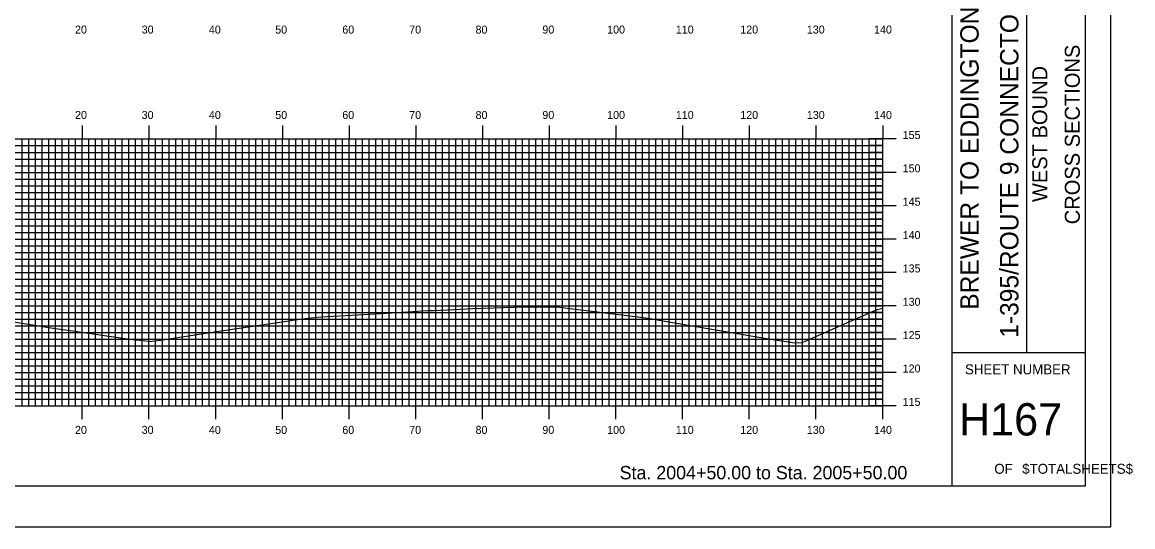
# Model space of a CAD drawing. Extents: x 851926 to 852269, y 366605 to 366825.
# Drawn here: x 852103 to 852269.5, y 366604.9 to 366680.6 of the extents above; entities that cross this region are included whole.
import ezdxf

# ---------------------------------------------------------------- set-up
doc = ezdxf.new("R2010")
doc.units = 0
for name, color, linetype in [('BORDER', 7, 'Continuous'), ('H_V ANNOTATION', 7, 'Continuous'), ('M_Roadway_Centerline', 7, 'Continuous'), ('MAJOR', 7, 'Continuous'), ('MINOR', 7, 'Continuous'), ('PLOT BOUNDARY', 7, 'Continuous'), ('S_Roadway_Centerline', 7, 'Continuous')]:
    doc.layers.add(name, color=color, linetype=linetype)

msp = doc.modelspace()

# ---------------------------------------------------------------- linework, layer by layer
at = {"layer": 'BORDER'}
for p, q in [((852242.36, 366611.06), (852242.36, 366821.06)), ((852253.55, 366631.06), (852253.55, 366701.06)), ((852242.36, 366631.06), (852262.36, 366631.06))]:
    msp.add_line(p, q, dxfattribs=at)
msp.add_lwpolyline([(851942.36, 366611.06), (852262.36, 366611.06), (852262.36, 366821.06), (851942.36, 366821.06)], close=True, dxfattribs=at)
at = {"layer": 'MAJOR'}
for p, q in [((852111.96, 366665.06), (852111.96, 366663.06)), ((852121.96, 366665.06), (852121.96, 366663.06)), ((852131.96, 366665.06), (852131.96, 366663.06)), ((852141.96, 366665.06), (852141.96, 366663.06)), ((852151.96, 366665.06), (852151.96, 366663.06)), ((852161.96, 366665.06), (852161.96, 366663.06)), ((852171.96, 366665.06), (852171.96, 366663.06)), ((852181.96, 366665.06), (852181.96, 366663.06)), ((852191.96, 366665.06), (852191.96, 366663.06)), ((852201.96, 366665.06), (852201.96, 366663.06)), ((852211.96, 366665.06), (852211.96, 366663.06)), ((852221.96, 366665.06), (852221.96, 366663.06)), ((852231.96, 366665.06), (852231.96, 366663.06)), ((851951.96, 366663.06), (852231.96, 366663.06)), ((851951.96, 366663.06), (852231.96, 366663.06)), ((852111.96, 366623.06), (852111.96, 366663.06)), ((852121.96, 366623.06), (852121.96, 366663.06)), ((852131.96, 366623.06), (852131.96, 366663.06)), ((852141.96, 366623.06), (852141.96, 366663.06)), ((852151.96, 366623.06), (852151.96, 366663.06)), ((852161.96, 366623.06), (852161.96, 366663.06)), ((852171.96, 366623.06), (852171.96, 366663.06)), ((852181.96, 366623.06), (852181.96, 366663.06)), ((852191.96, 366623.06), (852191.96, 366663.06)), ((852201.96, 366623.06), (852201.96, 366663.06)), ((852211.96, 366623.06), (852211.96, 366663.06)), ((852221.96, 366623.06), (852221.96, 366663.06)), ((852233.97, 366663.06), (852229.96, 366663.06)), ((852231.96, 366623.06), (852231.96, 366663.06)), ((852231.96, 366623.06), (852231.96, 366663.06)), ((851951.96, 366658.06), (852231.96, 366658.06)), ((852233.97, 366658.06), (852229.96, 366658.06)), ((851951.96, 366653.06), (852231.96, 366653.06)), ((852233.97, 366653.06), (852229.96, 366653.06)), ((851951.96, 366648.06), (852231.96, 366648.06)), ((852233.97, 366648.06), (852229.96, 366648.06)), ((851951.96, 366643.06), (852231.96, 366643.06)), ((852233.97, 366643.06), (852229.96, 366643.06)), ((851951.96, 366638.06), (852231.96, 366638.06)), ((852233.97, 366638.06), (852229.96, 366638.06)), ((851951.96, 366633.06), (852231.96, 366633.06)), ((852233.97, 366633.06), (852229.96, 366633.06)), ((851951.96, 366628.06), (852231.96, 366628.06)), ((852233.97, 366628.06), (852229.96, 366628.06)), ((851951.96, 366623.06), (852231.96, 366623.06)), ((851951.96, 366623.06), (852231.96, 366623.06)), ((852111.96, 366621.05), (852111.96, 366623.06)), ((852121.96, 366621.05), (852121.96, 366623.06)), ((852131.96, 366621.05), (852131.96, 366623.06)), ((852141.96, 366621.05), (852141.96, 366623.06)), ((852151.96, 366621.05), (852151.96, 366623.06)), ((852161.96, 366621.05), (852161.96, 366623.06)), ((852171.96, 366621.05), (852171.96, 366623.06)), ((852181.96, 366621.05), (852181.96, 366623.06)), ((852191.96, 366621.05), (852191.96, 366623.06)), ((852201.96, 366621.05), (852201.96, 366623.06)), ((852211.96, 366621.05), (852211.96, 366623.06)), ((852221.96, 366621.05), (852221.96, 366623.06)), ((852233.97, 366623.06), (852229.96, 366623.06)), ((852231.96, 366621.05), (852231.96, 366623.06))]:
    msp.add_line(p, q, dxfattribs=at)
at = {"layer": 'MINOR'}
for p, q in [((852102.96, 366623.06), (852102.96, 366663.06)), ((852103.96, 366623.06), (852103.96, 366663.06)), ((852104.96, 366623.06), (852104.96, 366663.06)), ((852105.96, 366623.06), (852105.96, 366663.06)), ((852106.96, 366623.06), (852106.96, 366663.06)), ((852107.96, 366623.06), (852107.96, 366663.06)), ((852108.96, 366623.06), (852108.96, 366663.06)), ((852109.96, 366623.06), (852109.96, 366663.06)), ((852110.96, 366623.06), (852110.96, 366663.06)), ((852112.96, 366623.06), (852112.96, 366663.06)), ((852113.96, 366623.06), (852113.96, 366663.06)), ((852114.96, 366623.06), (852114.96, 366663.06)), ((852115.96, 366623.06), (852115.96, 366663.06)), ((852116.96, 366623.06), (852116.96, 366663.06)), ((852117.96, 366623.06), (852117.96, 366663.06)), ((852118.96, 366623.06), (852118.96, 366663.06)), ((852119.96, 366623.06), (852119.96, 366663.06)), ((852120.96, 366623.06), (852120.96, 366663.06)), ((852122.96, 366623.06), (852122.96, 366663.06)), ((852123.96, 366623.06), (852123.96, 366663.06)), ((852124.96, 366623.06), (852124.96, 366663.06)), ((852125.96, 366623.06), (852125.96, 366663.06)), ((852126.96, 366623.06), (852126.96, 366663.06)), ((852127.96, 366623.06), (852127.96, 366663.06)), ((852128.96, 366623.06), (852128.96, 366663.06)), ((852129.96, 366623.06), (852129.96, 366663.06)), ((852130.96, 366623.06), (852130.96, 366663.06)), ((852132.96, 366623.06), (852132.96, 366663.06)), ((852133.96, 366623.06), (852133.96, 366663.06)), ((852134.96, 366623.06), (852134.96, 366663.06)), ((852135.96, 366623.06), (852135.96, 366663.06)), ((852136.96, 366623.06), (852136.96, 366663.06)), ((852137.96, 366623.06), (852137.96, 366663.06)), ((852138.96, 366623.06), (852138.96, 366663.06)), ((852139.96, 366623.06), (852139.96, 366663.06)), ((852140.96, 366623.06), (852140.96, 366663.06)), ((852142.96, 366623.06), (852142.96, 366663.06)), ((852143.96, 366623.06), (852143.96, 366663.06)), ((852144.96, 366623.06), (852144.96, 366663.06)), ((852145.96, 366623.06), (852145.96, 366663.06)), ((852146.96, 366623.06), (852146.96, 366663.06)), ((852147.96, 366623.06), (852147.96, 366663.06)), ((852148.96, 366623.06), (852148.96, 366663.06)), ((852149.96, 366623.06), (852149.96, 366663.06)), ((852150.96, 366623.06), (852150.96, 366663.06)), ((852152.96, 366623.06), (852152.96, 366663.06)), ((852153.96, 366623.06), (852153.96, 366663.06)), ((852154.96, 366623.06), (852154.96, 366663.06)), ((852155.96, 366623.06), (852155.96, 366663.06)), ((852156.96, 366623.06), (852156.96, 366663.06)), ((852157.96, 366623.06), (852157.96, 366663.06)), ((852158.96, 366623.06), (852158.96, 366663.06)), ((852159.96, 366623.06), (852159.96, 366663.06)), ((852160.96, 366623.06), (852160.96, 366663.06)), ((852162.96, 366623.06), (852162.96, 366663.06)), ((852163.96, 366623.06), (852163.96, 366663.06)), ((852164.96, 366623.06), (852164.96, 366663.06)), ((852165.96, 366623.06), (852165.96, 366663.06)), ((852166.96, 366623.06), (852166.96, 366663.06)), ((852167.96, 366623.06), (852167.96, 366663.06)), ((852168.96, 366623.06), (852168.96, 366663.06)), ((852169.96, 366623.06), (852169.96, 366663.06)), ((852170.96, 366623.06), (852170.96, 366663.06)), ((852172.96, 366623.06), (852172.96, 366663.06)), ((852173.96, 366623.06), (852173.96, 366663.06)), ((852174.96, 366623.06), (852174.96, 366663.06)), ((852175.96, 366623.06), (852175.96, 366663.06)), ((852176.96, 366623.06), (852176.96, 366663.06)), ((852177.96, 366623.06), (852177.96, 366663.06)), ((852178.96, 366623.06), (852178.96, 366663.06)), ((852179.96, 366623.06), (852179.96, 366663.06)), ((852180.96, 366623.06), (852180.96, 366663.06)), ((852182.96, 366623.06), (852182.96, 366663.06)), ((852183.96, 366623.06), (852183.96, 366663.06)), ((852184.96, 366623.06), (852184.96, 366663.06)), ((852185.96, 366623.06), (852185.96, 366663.06)), ((852186.96, 366623.06), (852186.96, 366663.06)), ((852187.96, 366623.06), (852187.96, 366663.06)), ((852188.96, 366623.06), (852188.96, 366663.06)), ((852189.96, 366623.06), (852189.96, 366663.06)), ((852190.96, 366623.06), (852190.96, 366663.06)), ((852192.96, 366623.06), (852192.96, 366663.06)), ((852193.96, 366623.06), (852193.96, 366663.06)), ((852194.96, 366623.06), (852194.96, 366663.06)), ((852195.96, 366623.06), (852195.96, 366663.06)), ((852196.96, 366623.06), (852196.96, 366663.06)), ((852197.96, 366623.06), (852197.96, 366663.06)), ((852198.96, 366623.06), (852198.96, 366663.06)), ((852199.96, 366623.06), (852199.96, 366663.06)), ((852200.96, 366623.06), (852200.96, 366663.06)), ((852202.96, 366623.06), (852202.96, 366663.06)), ((852203.96, 366623.06), (852203.96, 366663.06)), ((852204.96, 366623.06), (852204.96, 366663.06)), ((852205.96, 366623.06), (852205.96, 366663.06)), ((852206.96, 366623.06), (852206.96, 366663.06)), ((852207.96, 366623.06), (852207.96, 366663.06)), ((852208.96, 366623.06), (852208.96, 366663.06)), ((852209.96, 366623.06), (852209.96, 366663.06)), ((852210.96, 366623.06), (852210.96, 366663.06)), ((852212.96, 366623.06), (852212.96, 366663.06)), ((852213.96, 366623.06), (852213.96, 366663.06)), ((852214.96, 366623.06), (852214.96, 366663.06)), ((852215.96, 366623.06), (852215.96, 366663.06)), ((852216.96, 366623.06), (852216.96, 366663.06)), ((852217.96, 366623.06), (852217.96, 366663.06)), ((852218.96, 366623.06), (852218.96, 366663.06)), ((852219.96, 366623.06), (852219.96, 366663.06)), ((852220.96, 366623.06), (852220.96, 366663.06)), ((852222.96, 366623.06), (852222.96, 366663.06)), ((852223.96, 366623.06), (852223.96, 366663.06)), ((852224.96, 366623.06), (852224.96, 366663.06)), ((852225.96, 366623.06), (852225.96, 366663.06)), ((852226.96, 366623.06), (852226.96, 366663.06)), ((852227.96, 366623.06), (852227.96, 366663.06)), ((852228.96, 366623.06), (852228.96, 366663.06)), ((852229.96, 366623.06), (852229.96, 366663.06)), ((852230.96, 366623.06), (852230.96, 366663.06)), ((851951.96, 366662.06), (852231.96, 366662.06)), ((851951.96, 366661.06), (852231.96, 366661.06)), ((852231.96, 366662.06), (852229.96, 366662.06)), ((852231.96, 366661.06), (852229.96, 366661.06)), ((851951.96, 366660.06), (852231.96, 366660.06)), ((852231.96, 366660.06), (852229.96, 366660.06)), ((851951.96, 366659.06), (852231.96, 366659.06)), ((852231.96, 366659.06), (852229.96, 366659.06)), ((851951.96, 366657.06), (852231.96, 366657.06)), ((851951.96, 366656.06), (852231.96, 366656.06)), ((852231.96, 366657.06), (852229.96, 366657.06)), ((852231.96, 366656.06), (852229.96, 366656.06)), ((851951.96, 366655.06), (852231.96, 366655.06)), ((852231.96, 366655.06), (852229.96, 366655.06)), ((851951.96, 366654.06), (852231.96, 366654.06)), ((852231.96, 366654.06), (852229.96, 366654.06)), ((851951.96, 366652.06), (852231.96, 366652.06)), ((851951.96, 366651.06), (852231.96, 366651.06)), ((852231.96, 366652.06), (852229.96, 366652.06)), ((852231.96, 366651.06), (852229.96, 366651.06)), ((851951.96, 366650.06), (852231.96, 366650.06)), ((852231.96, 366650.06), (852229.96, 366650.06)), ((851951.96, 366649.06), (852231.96, 366649.06)), ((852231.96, 366649.06), (852229.96, 366649.06)), ((851951.96, 366647.06), (852231.96, 366647.06)), ((851951.96, 366646.06), (852231.96, 366646.06)), ((852231.96, 366647.06), (852229.96, 366647.06)), ((852231.96, 366646.06), (852229.96, 366646.06)), ((851951.96, 366645.06), (852231.96, 366645.06)), ((852231.96, 366645.06), (852229.96, 366645.06)), ((851951.96, 366644.06), (852231.96, 366644.06)), ((852231.96, 366644.06), (852229.96, 366644.06)), ((851951.96, 366642.06), (852231.96, 366642.06)), ((851951.96, 366641.06), (852231.96, 366641.06)), ((852231.96, 366642.06), (852229.96, 366642.06)), ((852231.96, 366641.06), (852229.96, 366641.06)), ((851951.96, 366640.06), (852231.96, 366640.06)), ((852231.96, 366640.06), (852229.96, 366640.06)), ((851951.96, 366639.06), (852231.96, 366639.06)), ((852231.96, 366639.06), (852229.96, 366639.06)), ((851951.96, 366637.06), (852231.96, 366637.06)), ((851951.96, 366636.06), (852231.96, 366636.06)), ((852231.96, 366637.06), (852229.96, 366637.06)), ((852231.96, 366636.06), (852229.96, 366636.06)), ((851951.96, 366635.06), (852231.96, 366635.06)), ((852231.96, 366635.06), (852229.96, 366635.06)), ((851951.96, 366634.06), (852231.96, 366634.06)), ((852231.96, 366634.06), (852229.96, 366634.06)), ((851951.96, 366632.06), (852231.96, 366632.06)), ((851951.96, 366631.06), (852231.96, 366631.06)), ((852231.96, 366632.06), (852229.96, 366632.06)), ((852231.96, 366631.06), (852229.96, 366631.06)), ((851951.96, 366630.06), (852231.96, 366630.06)), ((852231.96, 366630.06), (852229.96, 366630.06)), ((851951.96, 366629.06), (852231.96, 366629.06)), ((852231.96, 366629.06), (852229.96, 366629.06)), ((851951.96, 366627.06), (852231.96, 366627.06)), ((851951.96, 366626.06), (852231.96, 366626.06)), ((852231.96, 366627.06), (852229.96, 366627.06)), ((852231.96, 366626.06), (852229.96, 366626.06)), ((851951.96, 366625.06), (852231.96, 366625.06)), ((852231.96, 366625.06), (852229.96, 366625.06)), ((851951.96, 366624.06), (852231.96, 366624.06)), ((852231.96, 366624.06), (852229.96, 366624.06))]:
    msp.add_line(p, q, dxfattribs=at)
at = {"layer": 'PLOT BOUNDARY'}
msp.add_lwpolyline([(851926.18, 366604.94), (852266.18, 366604.94), (852266.18, 366824.94), (851926.18, 366824.94)], close=True, dxfattribs=at)
at = {"layer": 'S_Roadway_Centerline'}
msp.add_lwpolyline([(852096.8, 366636.39), (852104.84, 366635.14), (852106.94, 366634.82), (852110.51, 366634.31), (852119.09, 366633.07), (852121.92, 366632.77), (852121.98, 366632.71), (852123.66, 366632.93), (852132.07, 366634.21), (852141.25, 366635.56), (852144.89, 366636.08), (852147.72, 366636.42), (852153.26, 366636.71), (852154.99, 366636.8), (852159.27, 366637.03), (852163.74, 366637.36), (852164.72, 366637.37), (852170.5, 366637.65), (852178.19, 366637.9), (852182.52, 366637.91), (852183.27, 366637.89), (852183.85, 366637.82), (852196.03, 366636.3), (852196.86, 366636.19), (852198.98, 366635.81), (852214.86, 366633.11), (852218.77, 366632.53), (852219.88, 366632.57), (852230.32, 366637.15), (852231.2, 366637.51), (852231.96, 366637.71)], dxfattribs=at)

# ---------------------------------------------------------------- texts
at = {"layer": 'BORDER'}
for s, height, p in [('1-395/ROUTE 9 CONNECTOR', 2.7557, (852252.32, 366633.26)), ('BREWER TO EDDINGTON', 2.7557, (852246.35, 366637.46)), ('CROSS SECTIONS', 2.25, (852261.52, 366650.28)), ('WEST BOUND', 2.25, (852256.64, 366653.61))]:
    msp.add_text(s, height=height, rotation=90, dxfattribs=at).set_placement(p)
for s, height, p in [('SHEET NUMBER', 1.4905, (852244.3, 366627.79)), ('H167', 4.839, (852243.4, 366618.62)), ('OF', 1.491, (852248.7, 366612.88)), ('$TOTALSHEETS$', 1.4905, (852252.88, 366612.88))]:
    msp.add_text(s, height=height, dxfattribs=at).set_placement(p)
at = {"layer": 'H_V ANNOTATION'}
for s, height, p in [('20', 1.2, (852110.87, 366678.86)), ('30', 1.2, (852120.86, 366678.86)), ('40', 1.2, (852130.94, 366678.86)), ('50', 1.2, (852140.89, 366678.86)), ('60', 1.2, (852150.94, 366678.86)), ('70', 1.2, (852160.97, 366678.86)), ('80', 1.2, (852170.92, 366678.86)), ('90', 1.2, (852180.94, 366678.86)), ('100', 1.2, (852190.65, 366678.86)), ('110', 1.2, (852200.95, 366678.86)), ('120', 1.2, (852210.61, 366678.86)), ('130', 1.2, (852220.59, 366678.86)), ('140', 1.2, (852230.67, 366678.86)), ('20', 1.2, (852110.87, 366666.06)), ('30', 1.2, (852120.86, 366666.06)), ('40', 1.2, (852130.94, 366666.06)), ('50', 1.2, (852140.89, 366666.06)), ('60', 1.2, (852150.94, 366666.06)), ('70', 1.2, (852160.97, 366666.06)), ('80', 1.2, (852170.92, 366666.06)), ('90', 1.2, (852180.94, 366666.06)), ('100', 1.2, (852190.65, 366666.06)), ('110', 1.2, (852200.95, 366666.06)), ('120', 1.2, (852210.61, 366666.06)), ('130', 1.2, (852220.59, 366666.06)), ('140', 1.2, (852230.67, 366666.06)), ('155', 1.2, (852234.96, 366663.06)), ('150', 1.2, (852234.96, 366658.06)), ('145', 1.2, (852234.96, 366653.06)), ('140', 1.2, (852234.96, 366648.06)), ('135', 1.2, (852234.96, 366643.06)), ('130', 1.2, (852234.96, 366638.06)), ('125', 1.2, (852234.96, 366633.06)), ('120', 1.2, (852234.96, 366628.06)), ('115', 1.2, (852234.96, 366623.06)), ('20', 1.2, (852110.87, 366618.86)), ('30', 1.2, (852120.86, 366618.86)), ('40', 1.2, (852130.94, 366618.86)), ('50', 1.2, (852140.89, 366618.86)), ('60', 1.2, (852150.94, 366618.86)), ('70', 1.2, (852160.97, 366618.86)), ('80', 1.2, (852170.92, 366618.86)), ('90', 1.2, (852180.94, 366618.86)), ('100', 1.2, (852190.65, 366618.86)), ('110', 1.2, (852200.95, 366618.86)), ('120', 1.2, (852210.61, 366618.86)), ('130', 1.2, (852220.59, 366618.86)), ('140', 1.2, (852230.67, 366618.86)), ('Sta. 2004+50.00 to Sta. 2005+50.00', 2.0004, (852192.52, 366612.05))]:
    msp.add_text(s, height=height, dxfattribs=at).set_placement(p)
at = {"layer": 'M_Roadway_Centerline'}
for s, p in [('C', (852163.73, 366637.36)), ('L', (852163.74, 366637.35))]:
    msp.add_text(s, height=0.0146, dxfattribs=at).set_placement(p)

doc.saveas('drawing.dxf')
